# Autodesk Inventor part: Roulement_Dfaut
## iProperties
Created: 2006-03
Part Number: Roulement_Dfaut
Document SubType Name: Modeling
Designer: Flavien MARTY
Author: Flavien MARTY
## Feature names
1. Base1
